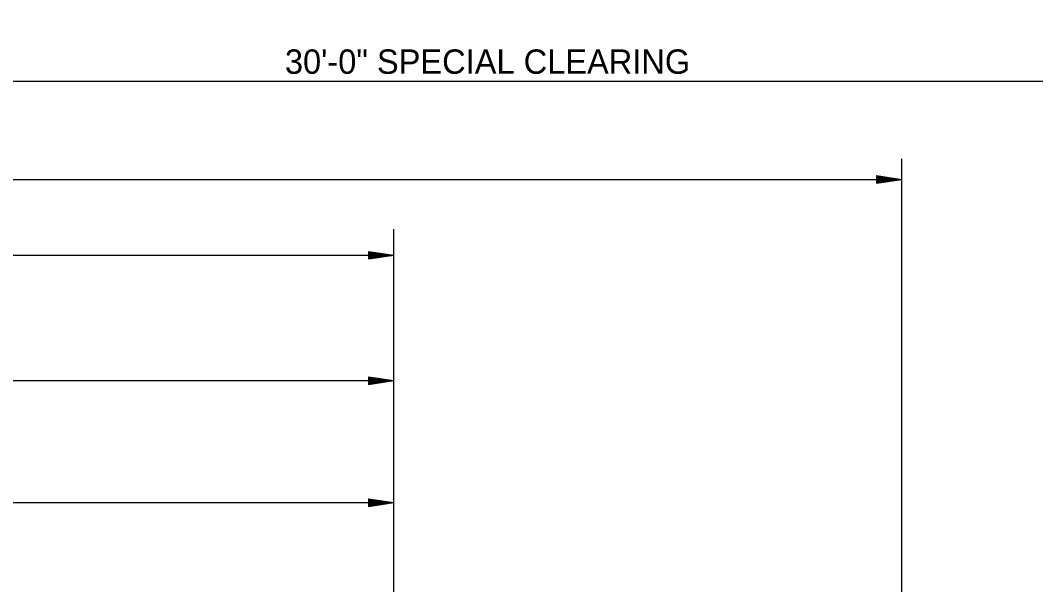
# Model space of a CAD drawing. Extents: x 1364961 to 1365294, y 367927 to 368034.
# Drawn here: x 1365056.37 to 1365080.37, y 367960.59 to 367973.93 of the extents above; entities that cross this region are included whole.
import ezdxf

# ---------------------------------------------------------------- set-up
doc = ezdxf.new("R2010")
doc.units = 0
doc.layers.add('Default', color=7, linetype='Continuous')

msp = doc.modelspace()

# ---------------------------------------------------------------- linework, layer by layer
at = {"layer": 'Default'}
for p, q in [((1365077.207, 367965.005), (1365077.207, 367970.652)), ((1365014.9, 367970.169), (1365077.207, 367970.169)), ((1365076.607, 367970.259), (1365077.207, 367970.169)), ((1365076.607, 367970.259), (1365076.607, 367970.079)), ((1365076.607, 367970.244), (1365077.107, 367970.169)), ((1365076.607, 367970.229), (1365077.004, 367970.169)), ((1365076.607, 367970.214), (1365076.904, 367970.169)), ((1365076.607, 367970.198), (1365076.802, 367970.169)), ((1365076.607, 367970.183), (1365076.702, 367970.169)), ((1365076.607, 367970.079), (1365077.207, 367970.169)), ((1365076.607, 367970.14), (1365076.802, 367970.169)), ((1365076.607, 367970.109), (1365077.004, 367970.169)), ((1365076.607, 367970.094), (1365077.107, 367970.169)), ((1365076.607, 367970.124), (1365076.904, 367970.169)), ((1365076.607, 367970.155), (1365076.702, 367970.169)), ((1365065.197, 367954.361), (1365065.197, 367968.995)), ((1365064.597, 367968.469), (1365065.197, 367968.379)), ((1365064.597, 367968.469), (1365064.597, 367968.289)), ((1365064.597, 367968.454), (1365065.097, 367968.379)), ((1365064.597, 367968.439), (1365064.994, 367968.379)), ((1365027.225, 367968.379), (1365065.197, 367968.379)), ((1365064.597, 367968.424), (1365064.894, 367968.379)), ((1365064.597, 367968.408), (1365064.792, 367968.379)), ((1365064.597, 367968.393), (1365064.692, 367968.379)), ((1365064.597, 367968.289), (1365065.197, 367968.379)), ((1365064.597, 367968.35), (1365064.792, 367968.379)), ((1365064.597, 367968.319), (1365064.994, 367968.379)), ((1365064.597, 367968.304), (1365065.097, 367968.379)), ((1365064.597, 367968.334), (1365064.894, 367968.379)), ((1365064.597, 367968.365), (1365064.692, 367968.379)), ((1365027.225, 367965.413), (1365065.197, 367965.413)), ((1365064.597, 367965.503), (1365065.197, 367965.413)), ((1365064.597, 367965.503), (1365064.597, 367965.323)), ((1365064.597, 367965.488), (1365065.097, 367965.413)), ((1365064.597, 367965.473), (1365064.994, 367965.413)), ((1365064.597, 367965.458), (1365064.894, 367965.413)), ((1365064.597, 367965.442), (1365064.792, 367965.413)), ((1365064.597, 367965.427), (1365064.692, 367965.413)), ((1365064.597, 367965.323), (1365065.197, 367965.413)), ((1365064.597, 367965.384), (1365064.792, 367965.413)), ((1365064.597, 367965.353), (1365064.994, 367965.413)), ((1365064.597, 367965.338), (1365065.097, 367965.413)), ((1365064.597, 367965.368), (1365064.894, 367965.413)), ((1365064.597, 367965.399), (1365064.692, 367965.413)), ((1365077.207, 367951.771), (1365077.207, 367965.005)), ((1365027.225, 367962.532), (1365065.197, 367962.532)), ((1365064.597, 367962.622), (1365065.197, 367962.532)), ((1365064.597, 367962.622), (1365064.597, 367962.442)), ((1365064.597, 367962.607), (1365065.097, 367962.532)), ((1365064.597, 367962.592), (1365064.994, 367962.532)), ((1365064.597, 367962.577), (1365064.894, 367962.532)), ((1365064.597, 367962.561), (1365064.792, 367962.532)), ((1365064.597, 367962.546), (1365064.692, 367962.532)), ((1365064.597, 367962.442), (1365065.197, 367962.532)), ((1365064.597, 367962.503), (1365064.792, 367962.532)), ((1365064.597, 367962.472), (1365064.994, 367962.532)), ((1365064.597, 367962.457), (1365065.097, 367962.532)), ((1365064.597, 367962.487), (1365064.894, 367962.532)), ((1365064.597, 367962.518), (1365064.692, 367962.532))]:
    msp.add_line(p, q, dxfattribs=at)
msp.add_lwpolyline([(1365055.203, 367972.489), (1365081.097, 367972.489), (1365081.954, 367973.929), (1365082.383, 367970.573), (1365082.811, 367972.489), (1365091.197, 367972.489)], dxfattribs=at)

# ---------------------------------------------------------------- texts
msp.add_text('30\'-0" SPECIAL CLEARING', height=0.576, dxfattribs=at).set_placement((1365062.624, 367972.665))

doc.saveas('drawing.dxf')
